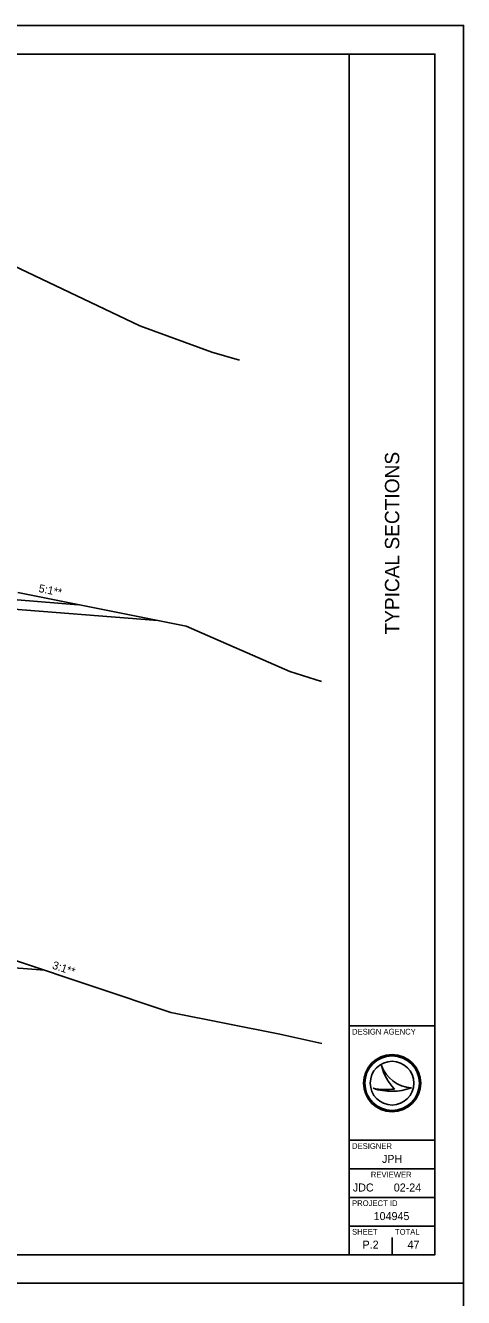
# Model space of a CAD drawing. Extents: x 0 to 219, y -66 to 66.
# Drawn here: x 79 to 102, y -0.8 to 66 of the extents above; entities that cross this region are included whole.
import ezdxf

# ---------------------------------------------------------------- set-up
doc = ezdxf.new("R2010")
doc.units = 0
for name, color, linetype in [('DT_X_Terrain_Ground_Line', 7, 'Continuous'), ('SH_Border', 7, 'Continuous'), ('SH_Cut_Line', 7, 'Continuous'), ('SH_Data', 7, 'Continuous'), ('TX_P_1', 7, 'Continuous'), ('TX_X_1', 7, 'Continuous'), ('XS_P_Finished_Grade', 7, 'Continuous')]:
    doc.layers.add(name, color=color, linetype=linetype)

msp = doc.modelspace()

# ---------------------------------------------------------------- linework, layer by layer
at = {"layer": 'DT_X_Terrain_Ground_Line'}
for points in [[(66.24, 55.379), (66.451, 55.388), (67.046, 55.307), (67.655, 55.24), (73.838, 54.521), (75.064, 54.15), (78.375, 53.406), (85.008, 50.236), (88.798, 48.861), (90.246, 48.432)], [(87.449, 34.473), (92.888, 32.095), (94.538, 31.575)], [(86.641, 14.214), (92.366, 13.066), (94.556, 12.581)]]:
    msp.add_lwpolyline(points, dxfattribs=at)
at = {"layer": 'SH_Border'}
for p, q in [((96, 1.5), (96, 64.5)), ((96, 13.5), (100.5, 13.5)), ((96, 7.5), (100.5, 7.5)), ((96, 6), (100.5, 6)), ((96, 4.5), (100.5, 4.5)), ((96, 3), (100.5, 3))]:
    msp.add_line(p, q, dxfattribs=at)
msp.add_lwpolyline([(4.5, 64.5), (100.5, 64.5), (100.5, 1.5), (4.5, 1.5)], close=True, dxfattribs=at)
at = {"layer": 'SH_Cut_Line'}
for points in [[(0, 0), (102, 0), (102, 66), (0, 66)], [(0, -66), (102, -66), (102, 0), (0, 0)]]:
    msp.add_lwpolyline(points, close=True, dxfattribs=at)
at = {"layer": 'SH_Data'}
for p, q in [((97.702, 11.429), (97.702, 11.429)), ((97.252, 10.229), (97.251, 10.229)), ((98.25, 10.5), (98.25, 10.5)), ((99.262, 10.256), (99.262, 10.256)), ((97.125, 2.025), (97.125, 2.025)), ((98.25, 1.5), (98.25, 2.4))]:
    msp.add_line(p, q, dxfattribs=at)
for radius in [1.5, 1.43, 1.43, 1.147]:
    msp.add_circle((98.25, 10.5), radius, dxfattribs=at)
for centre, radius, start, end in [((99.348, 11.993), 1.74, 198.92567, 198.93195), ((100.04, 11.91), 2.387, 191.63793, 191.64215), ((99.348, 11.993), 1.74, 198.93195, 267.16574), ((100.04, 11.91), 2.387, 191.64215, 226.09467), ((98.218, 13.11), 3.039, 251.45274, 251.45764), ((98.218, 13.11), 3.039, 251.45764, 290.08324), ((97.944, 13.963), 3.798, 259.49639, 259.49952), ((97.944, 13.963), 3.798, 259.49952, 276.66723)]:
    msp.add_arc(centre, radius, start, end, dxfattribs=at)
at = {"layer": 'TX_P_1'}
for p, q in [((68.25, 36.689), (81.776, 35.607)), ((68.25, 36.188), (85.956, 34.771)), ((68.25, 17.362), (80.021, 16.421))]:
    msp.add_line(p, q, dxfattribs=at)
at = {"layer": 'XS_P_Finished_Grade'}
for p, q in [((78.607, 36.241), (87.449, 34.473)), ((78.498, 16.928), (86.641, 14.214))]:
    msp.add_line(p, q, dxfattribs=at)

# ---------------------------------------------------------------- texts
at = {"layer": 'SH_Data'}
msp.add_text('TYPICAL SECTIONS', height=0.75, rotation=90, dxfattribs=at).set_placement((98.625, 34.039))
for s, height, p in [('DESIGN AGENCY', 0.3, (96.15, 13.05)), ('DESIGNER', 0.3, (96.15, 7.05)), ('JPH', 0.42, (97.719, 6.315)), ('REVIEWER', 0.3, (97.135, 5.55)), ('JDC', 0.42, (96.191, 4.815)), ('02-24', 0.42, (98.339, 4.815)), ('PROJECT ID', 0.3, (96.15, 4.05)), ('104945', 0.42, (97.283, 3.315)), ('SHEET', 0.3, (96.15, 2.55)), ('TOTAL', 0.3, (98.4, 2.55)), ('P.2', 0.42, (96.7, 1.815)), ('47', 0.42, (99.062, 1.815))]:
    msp.add_text(s, height=height, dxfattribs=at).set_placement(p)
at = {"layer": 'TX_P_1'}
msp.add_text('5:1**', height=0.42, rotation=348.69007, dxfattribs=at).set_placement((79.68, 36.274))
at = {"layer": 'TX_X_1'}
msp.add_text('3:1**', height=0.42, rotation=341.56505, dxfattribs=at).set_placement((80.385, 16.521))

doc.saveas('drawing.dxf')
